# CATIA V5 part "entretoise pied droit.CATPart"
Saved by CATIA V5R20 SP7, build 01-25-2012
Part number: entretoise pied droit
Bounding box of the stored display mesh (mm): x 19.898 to 37.465, y -79 to -65, z -1.427 to 10.253
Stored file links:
  F:\Travaux\Modélisations\CFAO_2011\CFAO_2011_MMS\CFAO_2011_MMS_DONE\CFAO_2011_MMS_jboiteux\Catia\entretoise pied droit.CATPart
  U:\finthinkmotion\stepper.CATProduct
  F:\Travaux\Modélisations\CFAO_2011\CFAO_2011_MMS\CFAO_2011_MMS_DONE\CFAO_2011_MMS_jboiteux\Catia\Part1.CATPart
  F:\Travaux\Modélisations\CFAO_2011\CFAO_2011_MMS\CFAO_2011_MMS_DONE\CFAO_2011_MMS_jboiteux\Catia\bati.CATPart
  F:\Travaux\Modélisations\CFAO_2011\CFAO_2011_MMS\CFAO_2011_MMS_DONE\CFAO_2011_MMS_jboiteux\Catia\Part2.CATPart
  F:\Travaux\Modélisations\CFAO_2011\CFAO_2011_MMS\CFAO_2011_MMS_DONE\CFAO_2011_MMS_jboiteux\Catia\compteur.CATPart
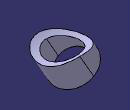
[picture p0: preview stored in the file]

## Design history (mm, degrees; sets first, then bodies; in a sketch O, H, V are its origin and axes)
Parameters
  rayontube = 9 mm {= External.royontubebati}
External parameters (linked from other documents)
  External.royontubebati = 9 mm
Set1
  Plane1: linked copy from another document
  Point1: linked copy from another document
  Plane2: linked copy from another document
  Plane3: linked copy from another document
  DatumSurface1: linked copy from another document
  Plane4: linked copy from another document
Body1 (main body)
  Plane5: stored without definition
  Sketch1 on Plane1, origin (2.8878, 0, 5.0017), H (0, 1, 0), V (-0.866, 0, 0.5)
    circle A1 centre (-72, -21.4454) radius 5
    point P1 (-72, -21.4454)
    reference projected point E1 (-72, -21.4454) from Point1
    circle A2 centre (-72, -21.4454) radius 7
    point P2 (-72, -21.4454)
    reference projected point E2 (-72, -21.4454) from Point1
    radius A1 = 5 {= rayontube *5/9}
    radius A2 = 7 {= rayontube *5/9+2mm}
    coincidence: E1 P1, E2 P2
  Pad1: profile Sketch1, direction (0.5, 0, 0.866), up to Plane2, opposite side length -9 {= -rayontube}
  Sketch2 on Plane3, origin (42.31, 0, 0), H (0, 1, 0), V (0, 0, 1)
    projected circle E1 centre (-72, 20) radius 12 from edge of DatumSurface1
  Pocket1: profile Sketch2, direction (-1, 0, 0), up to Plane4, opposite side length 47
